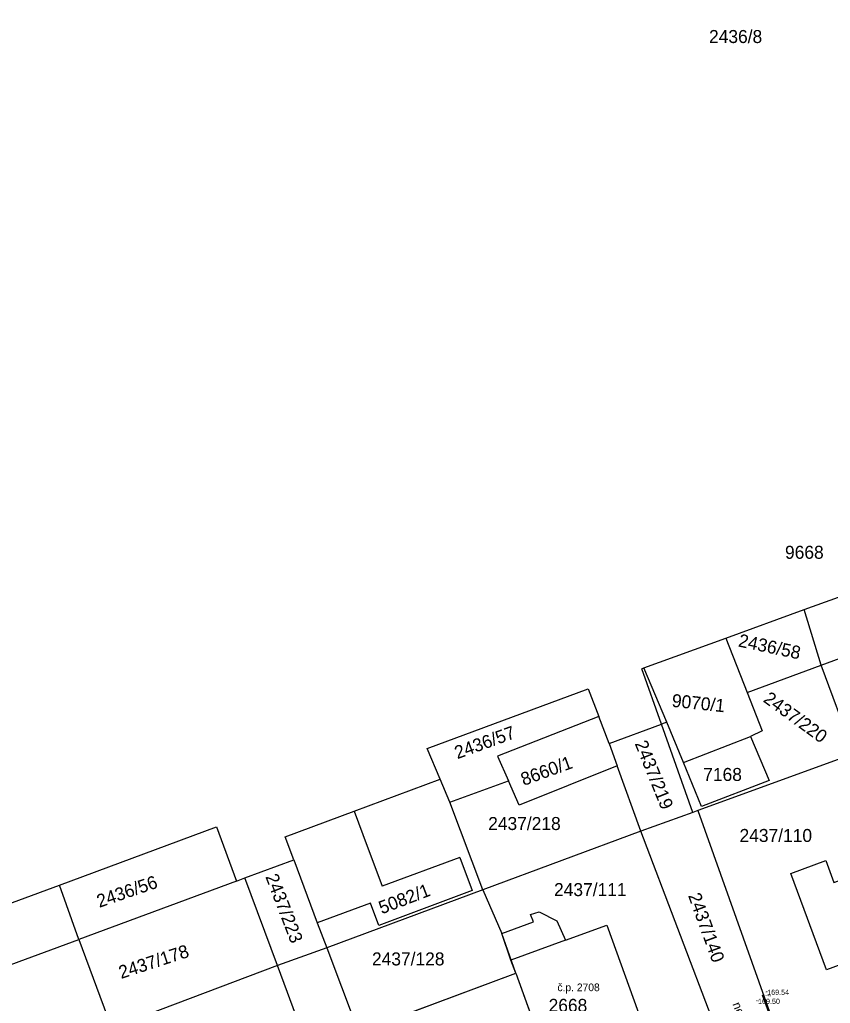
# Model space of a CAD drawing. Extents: x -566117 to -565580, y -1202428 to -1201938.
# Drawn here: x -566017 to -565948.4, y -1202054.3 to -1201971.1 of the extents above; entities that cross this region are included whole.
import ezdxf

# ---------------------------------------------------------------- set-up
doc = ezdxf.new("R2010")
doc.units = 0
for name, color, linetype in [('Bod', 7, 'Continuous'), ('BUOVY_NEMĚŘ', 7, 'Continuous'), ('Implicitní', 7, 'Continuous'), ('Katastr', 7, 'Continuous'), ('Kod', 7, 'Continuous'), ('Oplocení', 7, 'Continuous'), ('POMOC_POPIS', 7, 'Continuous'), ('Výška', 7, 'Continuous'), ('Zpevněné plohy', 7, 'Continuous'), ('Číslo', 7, 'Continuous'), ('Číslo popisné', 7, 'Continuous')]:
    doc.layers.add(name, color=color, linetype=linetype)

# ---------------------------------------------------------------- blocks, each defined once
blk = doc.blocks.new('A$C69D74C1E')
at = {"layer": 'Katastr'}
for p, q in [((107.68, 45.02), (114.32, 47.46)), ((115.74, 42.75), (114.32, 47.46)), ((115.74, 42.75), (124.34, 45.92)), ((107.68, 45.02), (109.48, 40.43)), ((102.69, 37.93), (100.75, 42.52)), ((109.48, 40.43), (115.74, 42.75)), ((118.51, 35.25), (115.74, 42.75)), ((96.95, 38.42), (88.38, 35.05)), ((97.8, 36.12), (96.95, 38.42)), ((97.8, 36.12), (102.23, 37.76)), ((104.88, 30.28), (102.23, 37.76)), ((104.1, 34.52), (109.78, 36.71)), ((97.8, 36.12), (98.5, 34.24)), ((88.38, 35.05), (89.29, 32.98)), ((118.51, 35.25), (105.31, 30.45)), ((98.5, 34.24), (90.2, 30.92)), ((100.48, 28.71), (98.5, 34.24)), ((84.35, 31.15), (83.51, 33.12)), ((84.35, 31.15), (89.29, 32.98)), ((90.2, 30.92), (89.29, 32.98)), ((87.14, 23.75), (84.35, 31.15)), ((76.25, 30.4), (76.98, 28.44)), ((104.88, 30.28), (100.48, 28.71)), ((105.31, 30.45), (104.88, 30.28)), ((105.31, 30.45), (112.72, 9.65)), ((76.98, 28.44), (78.62, 24.05)), ((100.48, 28.71), (87.14, 23.75)), ((108.29, 8.21), (100.48, 28.71)), ((67.01, 24.75), (71.14, 26.28)), ((85.19, 26.49), (78.62, 24.05)), ((85.19, 26.49), (86.23, 23.7)), ((52.95, 19.56), (51.32, 24.14)), ((66.28, 24.48), (52.95, 19.56)), ((66.28, 24.48), (67.01, 24.75)), ((69.76, 17.35), (67.01, 24.75)), ((87.14, 23.75), (73.93, 18.84)), ((86.23, 23.7), (78.34, 20.73)), ((87.14, 23.75), (88.74, 20.05)), ((77.63, 22.62), (73.11, 20.96)), ((78.34, 20.73), (77.63, 22.62)), ((88.74, 20.05), (91.41, 21.03)), ((38.68, 14.28), (52.95, 19.56)), ((52.95, 19.56), (55.73, 12.06)), ((94.11, 19.48), (89.51, 17.79)), ((73.93, 18.84), (69.76, 17.35)), ((73.93, 18.84), (76.6, 11.74)), ((69.76, 17.35), (55.73, 12.06)), ((77.39, -3.22), (69.76, 17.35)), ((76.6, 11.74), (89.91, 16.7)), ((89.91, 16.7), (92.97, 8.23))]:
    blk.add_line(p, q, dxfattribs=at)
for points in [[(114.32, 47.46), (128.13, 52.42), (128.19, 52.19)], [(102.23, 37.76), (100.58, 42.44), (100.75, 42.52), (107.68, 45.02)], [(83.51, 33.12), (82.41, 35.7), (96.04, 40.75), (96.95, 38.42)], [(109.48, 40.43), (110.75, 37.19), (109.78, 36.71)], [(104.1, 34.52), (102.69, 37.93), (102.23, 37.76)], [(109.78, 36.71), (111.34, 33), (105.61, 30.8), (104.1, 34.52)], [(71.14, 26.28), (70.42, 28.23), (76.25, 30.4), (83.51, 33.12)], [(51.32, 24.14), (64.6, 29.07), (66.28, 24.48)], [(71.14, 26.28), (73.11, 20.96), (73.93, 18.84)], [(124.34, 19.99), (116.2, 16.98), (113.18, 25.14), (116.15, 26.23), (116.83, 24.37), (121.95, 26.24)], [(38.68, 14.28), (37, 18.86), (51.32, 24.14)], [(91.41, 21.03), (91.15, 21.66), (91.9, 21.9), (93.4, 21.14), (94.11, 19.48), (97.63, 20.77)], [(89.91, 16.7), (89.51, 17.79), (88.74, 20.05)], [(97.63, 20.77), (101.04, 11.33), (92.97, 8.23)]]:
    blk.add_lwpolyline(points, dxfattribs=at)
for s, p in [('2436/8', (106.26, 95.367)), ('9668', (112.687, 51.747)), ('7168', (105.77, 32.957)), ('2437/218', (87.58, 28.807)), ('2437/110', (108.84, 27.797)), ('2437/111', (93.15, 23.217)), ('2437/128', (77.75, 17.357)), ('2668', (92.69, 13.427))]:
    blk.add_text(s, height=1.1, dxfattribs=at).set_placement(p)
for s, rotation, p in [('2436/58', 348, (108.676, 44.339)), ('9070/1', 354, (103.073, 39.232)), ('2437/220', 324, (110.776, 39.707)), ('2436/57', 20, (84.975, 34.795)), ('2437/219', 292, (99.96, 36.127)), ('8660/1', 20, (90.585, 32.535)), ('2436/56', 19, (54.691, 22.227)), ('2437/223', 291, (68.722, 24.861)), ('5082/1', 21, (78.579, 21.672)), ('2437/140', 290, (104.475, 23.265)), ('2437/178', 18, (56.537, 16.209))]:
    blk.add_text(s, height=1.1, rotation=rotation, dxfattribs=at).set_placement(p)
blk = doc.blocks.new('POINT_DISPLAY')
at = {"layer": 'Implicitní'}
blk.add_line((0, 0), (0, 0), dxfattribs=at)

msp = doc.modelspace()

# ---------------------------------------------------------------- linework, layer by layer
at = {"layer": 'BUOVY_NEMĚŘ'}
for points in [[(-565942.98, -1202042.2), (-565940.59, -1202048.45), (-565948.73, -1202051.46), (-565951.75, -1202043.3), (-565948.78, -1202042.21), (-565948.1, -1202044.07)], [(-565975.02, -1202051.74), (-565976.19, -1202048.39), (-565973.52, -1202047.41), (-565973.78, -1202046.78), (-565973.03, -1202046.54), (-565971.53, -1202047.3), (-565970.82, -1202048.96), (-565967.3, -1202047.67), (-565963.89, -1202057.11), (-565971.96, -1202060.21)], [(-565988.33, -1202056.7), (-565975.02, -1202051.74), (-565971.96, -1202060.21), (-565980.13, -1202063.12), (-565985.19, -1202065.07), (-565988.33, -1202056.7)]]:
    msp.add_lwpolyline(points, dxfattribs=at)
at = {"layer": 'Oplocení'}
msp.add_line((-565954.186, -1202053.573), (-565952.338, -1202058.53), dxfattribs=at)
at = {"layer": 'Zpevněné plohy'}
for points in [[(-566046.233, -1202095.491), (-566045.931, -1202095.393), (-566043.978, -1202094.752), (-566040.389, -1202093.195), (-566035.531, -1202091.756), (-566028.975, -1202089.449), (-566022.404, -1202086.74), (-566013.877, -1202083.764), (-566006.988, -1202080.967), (-565999.231, -1202078.336), (-565993.39, -1202076.098), (-565982.391, -1202071.759), (-565967.94, -1202066.641), (-565949.498, -1202059.811), (-565935.388, -1202054.572), (-565926.049, -1202051.077), (-565917.958, -1202048.181), (-565909.827, -1202045.163), (-565898.95, -1202041.321), (-565888.732, -1202037.388), (-565879.759, -1202034.036), (-565869.081, -1202030.224), (-565859.242, -1202026.317), (-565849.297, -1202023.069), (-565843.932, -1202020.848), (-565836.631, -1202018.501), (-565830.04, -1202016.01), (-565822.89, -1202013.251), (-565816.476, -1202011.009), (-565808.989, -1202007.913), (-565802.143, -1202004.887), (-565798.059, -1202002.759), (-565793.947, -1202000.116), (-565789.34, -1201997.072), (-565785.134, -1201994.185), (-565781.539, -1201991.969), (-565778.045, -1201989.73), (-565773.319, -1201986.775), (-565768.281, -1201983.714), (-565761.544, -1201979.725), (-565754.374, -1201977.005), (-565748.201, -1201974.518), (-565743.713, -1201972.786), (-565741.115, -1201971.759), (-565739.444, -1201971.098)], [(-565976.764, -1202074.599), (-565975.068, -1202073.996), (-565970.908, -1202072.515), (-565960.65, -1202068.538), (-565946.466, -1202063.528), (-565932.832, -1202058.326), (-565923.028, -1202054.759), (-565915.71, -1202052.273), (-565903.782, -1202047.572), (-565889.735, -1202042.655), (-565875.782, -1202037.425), (-565865.226, -1202033.562), (-565857.124, -1202030.559), (-565849.222, -1202027.615), (-565843.807, -1202025.74), (-565838.67, -1202023.909), (-565834.175, -1202022.242), (-565830.509, -1202020.913), (-565828.358, -1202020.134)]]:
    msp.add_open_spline(points, degree=3, dxfattribs=at)

# ---------------------------------------------------------------- block references
at = {"layer": 'Bod'}
msp.add_blockref('POINT_DISPLAY', (-565954.186, -1202053.573), dxfattribs=at)
at = {"layer": 'Implicitní'}
msp.add_blockref('A$C69D74C1E', (-566064.93, -1202068.44), dxfattribs=at)

# ---------------------------------------------------------------- texts
at = {"layer": 'Kod'}
msp.add_text('ZABSET', height=0.13, dxfattribs=at).set_placement((-565953.927, -1202053.707))
at = {"layer": 'POMOC_POPIS'}
msp.add_text('nezp.cesta', height=0.75, rotation=290.99316, dxfattribs=at).set_placement((-565956.701, -1202054.351))
at = {"layer": 'Výška'}
for s, p in [('169.54', (-565953.749, -1202053.573)), ('169.50', (-565954.522, -1202054.339))]:
    msp.add_text(s, height=0.4375, dxfattribs=at).set_placement(p)
at = {"layer": 'Číslo'}
for s, p in [('384', (-565953.924, -1202053.364)), ('383', (-565954.697, -1202054.129))]:
    msp.add_text(s, height=0.13, dxfattribs=at).set_placement(p)
at = {"layer": 'Číslo popisné'}
msp.add_text('č.p. 2708', height=0.65, dxfattribs=at).set_placement((-565971.491, -1202053.263))

doc.saveas('drawing.dxf')
